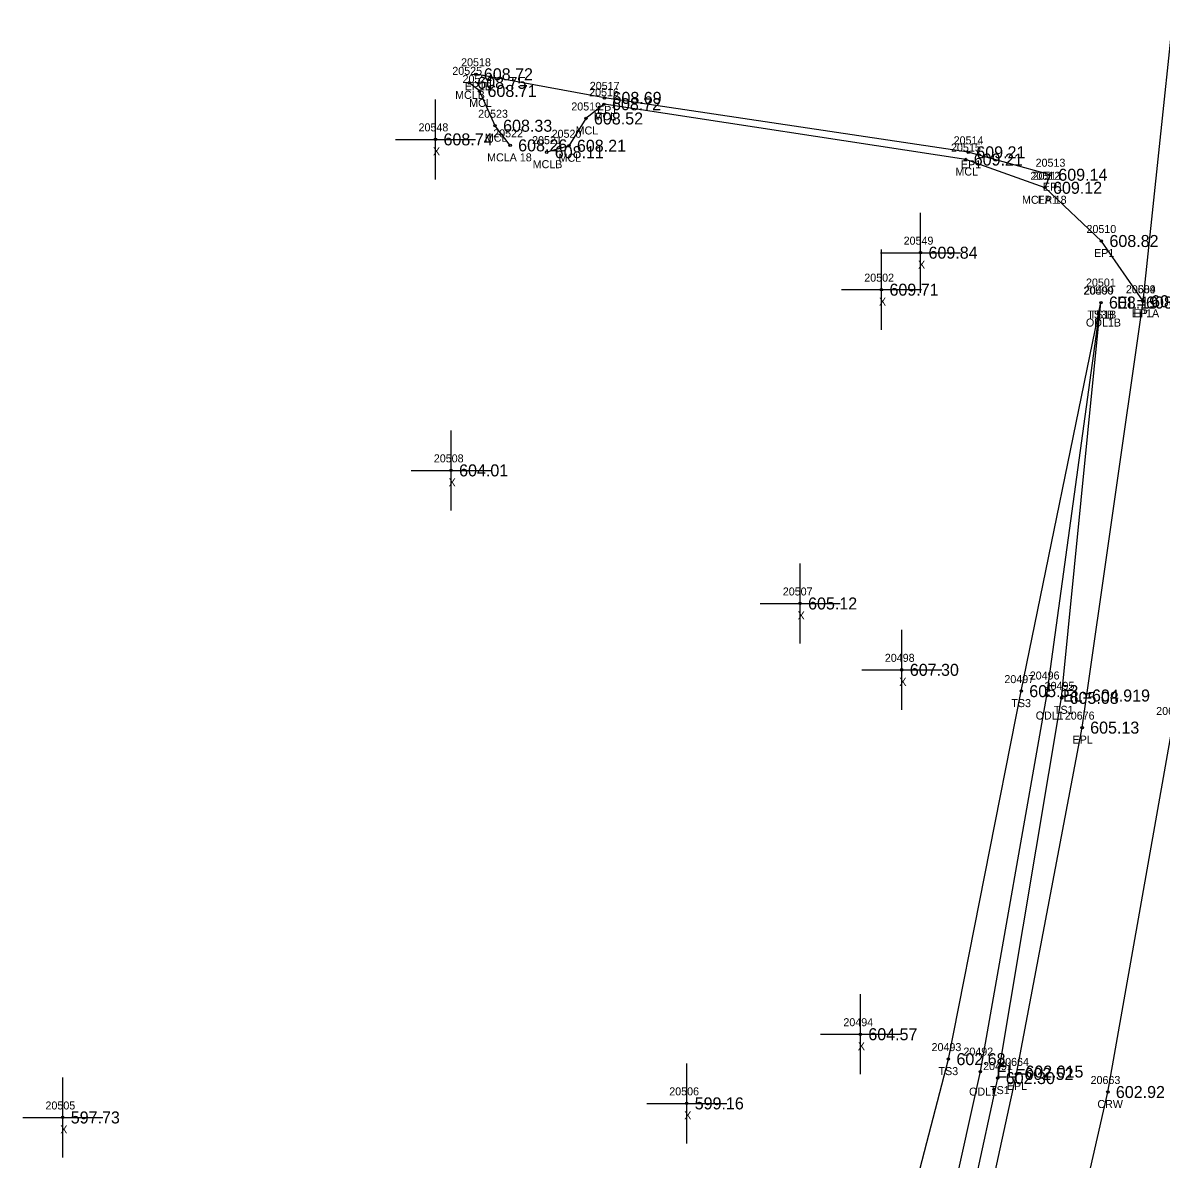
# Model space of a CAD drawing. Extents: x 1695443 to 1696344, y 1087542 to 1090645.
# Drawn here: x 1695674.7 to 1695817, y 1089816.1 to 1089958.1 of the extents above; entities that cross this region are included whole.
import ezdxf

# ---------------------------------------------------------------- set-up
doc = ezdxf.new("R2010")
doc.units = 0
for name, color, linetype in [('RD_DTM_BkLn1', 7, 'Continuous'), ('RD_DTM_BkLn2', 7, 'Continuous'), ('RD_DTM_BkLn_txCode', 7, 'Continuous'), ('RD_EX_Conc', 7, 'Continuous'), ('RD_EX_Conc_txCode', 7, 'Continuous'), ('RD_EX_H2O', 7, 'Continuous'), ('RD_EX_H2O_txCode', 7, 'Continuous'), ('RD_EX_Misc', 7, 'Continuous'), ('RD_EX_Misc_txCode', 7, 'Continuous'), ('RD_EX_Road', 7, 'Continuous'), ('RD_EX_Road_txCode', 7, 'Continuous'), ('RD_EX_TX_Conc_ELEV', 7, 'Continuous'), ('RD_EX_TX_H2O_ELEV', 7, 'Continuous'), ('RD_EX_TX_Misc_ELEV', 7, 'Continuous'), ('RD_EX_TX_Road_ELEV', 7, 'Continuous'), ('RD_HC_Survey_ELEV', 7, 'Continuous'), ('RD_HC_Survey_txCode', 7, 'Continuous'), ('RD_SMD_Locator', 7, 'Continuous')]:
    doc.layers.add(name, color=color, linetype=linetype)

msp = doc.modelspace()

# ---------------------------------------------------------------- linework, layer by layer
at = {"layer": 'RD_DTM_BkLn1'}
msp.add_lwpolyline([(1695813.78, 1089148.1), (1695785.55, 1089189.03), (1695758.89, 1089235.87), (1695740.64, 1089279.02), (1695725.17, 1089334.02), (1695718.27, 1089382.65), (1695717.41, 1089435.13), (1695722.03, 1089482.62), (1695732.64, 1089534.75), (1695759.85, 1089631.43), (1695787.11, 1089727.89), (1695798.89, 1089774.41), (1695810.31, 1089824.5), (1695818.49, 1089870.61), (1695825.85, 1089922.33), (1695831.69, 1089976.57), (1695835.49, 1090019.27), (1695844.06, 1090117.91), (1695852.56, 1090215.73), (1695861.78, 1090313.02), (1695870.8, 1090411.68), (1695879.44, 1090510.15), (1695888.04, 1090606.94)], dxfattribs=at)
at = {"layer": 'RD_DTM_BkLn2'}
for points in [[(1695696.87, 1089328.65), (1695685.13, 1089358.98), (1695692.41, 1089382.13), (1695691.76, 1089435.56), (1695699.73, 1089488.72), (1695712.17, 1089543.62), (1695742.06, 1089638.06), (1695765.36, 1089733.76), (1695777.86, 1089780.36), (1695790.39, 1089828.61), (1695799.49, 1089874.59), (1695809.45, 1089923.14)], [(1695802.49, 1089139.56), (1695797.31, 1089139.87), (1695796.55, 1089145.92), (1695767.85, 1089172.77), (1695752.08, 1089198.99), (1695743.04, 1089224.25), (1695723.93, 1089271.63), (1695706.46, 1089330), (1695701.78, 1089380.95), (1695703.12, 1089435.75), (1695708.88, 1089486.48), (1695720.72, 1089539.1), (1695747.1, 1089636.56), (1695773.41, 1089730.59), (1695786.04, 1089777.66), (1695796.55, 1089826.24), (1695804.53, 1089873.75), (1695809.45, 1089923.14)]]:
    msp.add_lwpolyline(points, dxfattribs=at)
at = {"layer": 'RD_EX_Conc'}
for points in [[(1695735.62, 1089942.78), (1695733.74, 1089945.23), (1695731.79, 1089949.58), (1695730.51, 1089950.59)], [(1695802.46, 1089937.48), (1695792.55, 1089941.01), (1695747.35, 1089947.92), (1695745.09, 1089946.14), (1695742.96, 1089942.73), (1695740.19, 1089941.93)]]:
    msp.add_lwpolyline(points, dxfattribs=at)
at = {"layer": 'RD_EX_H2O'}
msp.add_lwpolyline([(1695696.87, 1089328.65), (1695699.57, 1089380.43), (1695700.06, 1089435.96), (1695707.01, 1089487.43), (1695718.96, 1089539.87), (1695744.93, 1089637.33), (1695772.06, 1089731.31), (1695783.6, 1089778.47), (1695794.38, 1089827.05), (1695802.7, 1089874.04), (1695809.45, 1089923.14)], dxfattribs=at)
at = {"layer": 'RD_EX_Misc'}
for p, q in [((1695726.29, 1089938.53), (1695726.29, 1089948.53)), ((1695721.29, 1089943.53), (1695731.29, 1089943.53)), ((1695786.9, 1089924.37), (1695786.9, 1089934.37)), ((1695782.02, 1089919.75), (1695782.02, 1089929.75)), ((1695781.9, 1089929.37), (1695791.9, 1089929.37)), ((1695777.02, 1089924.75), (1695787.02, 1089924.75)), ((1695728.24, 1089897.17), (1695728.24, 1089907.17)), ((1695723.24, 1089902.17), (1695733.24, 1089902.17)), ((1695771.85, 1089880.54), (1695771.85, 1089890.54)), ((1695766.85, 1089885.54), (1695776.85, 1089885.54)), ((1695784.56, 1089872.25), (1695784.56, 1089882.25)), ((1695779.56, 1089877.25), (1695789.56, 1089877.25)), ((1695779.38, 1089826.72), (1695779.38, 1089836.72)), ((1695774.38, 1089831.72), (1695784.38, 1089831.72)), ((1695757.68, 1089818.08), (1695757.68, 1089828.08)), ((1695679.71, 1089816.32), (1695679.71, 1089826.32)), ((1695752.68, 1089823.08), (1695762.68, 1089823.08)), ((1695674.71, 1089821.32), (1695684.71, 1089821.32))]:
    msp.add_line(p, q, dxfattribs=at)
at = {"layer": 'RD_EX_Road'}
for points in [[(1695813.78, 1089148.1), (1695805.56, 1089142.08), (1695776.44, 1089183.94), (1695749.27, 1089231.88), (1695730.49, 1089275.72), (1695714.87, 1089332.12), (1695707.87, 1089381.72), (1695706.58, 1089435.34), (1695711.58, 1089484.26), (1695722.15, 1089537.59), (1695749.04, 1089634.88), (1695776.11, 1089730.43), (1695788.13, 1089777.42), (1695798.89, 1089826.76), (1695807.1, 1089870.03), (1695814.71, 1089923.3), (1695820.51, 1089978.16), (1695824.04, 1090019.79), (1695832.76, 1090119.06), (1695841.25, 1090216.76), (1695850.36, 1090314.41), (1695859.24, 1090411.82), (1695868.09, 1090511.63), (1695876.75, 1090608.38)], [(1695814.71, 1089923.3), (1695809.51, 1089930.83), (1695802.46, 1089937.48), (1695803.12, 1089939.11), (1695792.87, 1089941.91), (1695747.41, 1089948.71), (1695731.33, 1089951.66)]]:
    msp.add_lwpolyline(points, dxfattribs=at)
at = {"layer": 'RD_SMD_Locator'}
for centre in [(1695731.33, 1089951.66), (1695730.51, 1089950.59), (1695731.79, 1089949.58), (1695747.41, 1089948.71), (1695747.35, 1089947.92), (1695733.74, 1089945.23), (1695745.09, 1089946.14), (1695726.29, 1089943.53), (1695735.62, 1089942.78), (1695742.96, 1089942.73), (1695740.19, 1089941.93), (1695792.55, 1089941.01), (1695792.87, 1089941.91), (1695803.12, 1089939.11), (1695802.46, 1089937.48), (1695802.46, 1089937.48), (1695809.51, 1089930.83), (1695786.9, 1089929.37), (1695782.02, 1089924.75), (1695809.45, 1089923.14), (1695809.45, 1089923.14), (1695809.45, 1089923.14), (1695814.71, 1089923.3), (1695814.71, 1089923.3), (1695728.24, 1089902.17), (1695771.85, 1089885.54), (1695784.56, 1089877.25), (1695799.49, 1089874.59), (1695802.7, 1089874.04), (1695804.53, 1089873.75), (1695807.1, 1089870.03), (1695779.38, 1089831.72), (1695790.39, 1089828.61), (1695794.38, 1089827.05), (1695796.55, 1089826.24), (1695798.89, 1089826.76), (1695810.31, 1089824.5), (1695757.68, 1089823.08), (1695679.71, 1089821.32)]:
    msp.add_circle(centre, 0.15, dxfattribs=at)

# ---------------------------------------------------------------- texts
at = {"layer": 'RD_DTM_BkLn_txCode'}
for s, p in [('20500', (1695807.26, 1089924.14)), ('20499', (1695807.33, 1089924.14)), ('TS3B', (1695807.74, 1089921.14)), ('TS1B', (1695808.02, 1089921.14)), ('20497', (1695797.38, 1089875.59)), ('20495', (1695802.41, 1089874.75)), ('TS3', (1695798.25, 1089872.59)), ('TS1', (1695803.57, 1089871.75)), ('20493', (1695788.28, 1089829.61)), ('TS3', (1695789.15, 1089826.61)), ('20491', (1695794.72, 1089827.24)), ('TS1', (1695795.59, 1089824.24))]:
    msp.add_text(s, height=1, dxfattribs=at).set_placement(p)
at = {"layer": 'RD_EX_Conc_txCode'}
for s, p in [('20525', (1695728.39, 1089951.59)), ('20524', (1695729.67, 1089950.58)), ('MCLB', (1695728.74, 1089948.59)), ('20516', (1695745.49, 1089948.92)), ('MCL', (1695730.5, 1089947.58)), ('20519', (1695743.26, 1089947.14)), ('20523', (1695731.62, 1089946.23)), ('MCL', (1695746.05, 1089945.92)), ('MCL', (1695732.45, 1089943.23)), ('20522', (1695733.5, 1089943.78)), ('20521', (1695738.36, 1089942.93)), ('20520', (1695740.8, 1089943.73)), ('MCL', (1695743.8, 1089944.14)), ('20515', (1695790.71, 1089942.01)), ('MCLA 18', (1695732.74, 1089940.78)), ('MCL', (1695741.67, 1089940.73)), ('MCLB', (1695738.43, 1089939.93)), ('MCL', (1695791.26, 1089939.01)), ('20512', (1695800.63, 1089938.48)), ('MCLA 18', (1695799.58, 1089935.48))]:
    msp.add_text(s, height=1, dxfattribs=at).set_placement(p)
at = {"layer": 'RD_EX_H2O_txCode'}
for s, p in [('20501', (1695807.58, 1089925.14)), ('ODL1B', (1695807.57, 1089920.14)), ('20496', (1695800.55, 1089876.04)), ('ODL1', (1695801.29, 1089871.04)), ('20492', (1695792.26, 1089829.05)), ('ODL1', (1695792.97, 1089824.05))]:
    msp.add_text(s, height=1, dxfattribs=at).set_placement(p)
at = {"layer": 'RD_EX_Misc_txCode'}
for s, p in [('20548', (1695724.17, 1089944.53)), ('X', (1695725.97, 1089941.53)), ('20549', (1695784.79, 1089930.37)), ('X', (1695786.59, 1089927.37)), ('20502', (1695779.87, 1089925.75)), ('X', (1695781.71, 1089922.75)), ('20508', (1695726.08, 1089903.17)), ('X', (1695727.92, 1089900.17)), ('20507', (1695769.69, 1089886.54)), ('X', (1695771.54, 1089883.54)), ('20498', (1695782.44, 1089878.25)), ('X', (1695784.25, 1089875.25)), ('20494', (1695777.26, 1089832.72)), ('X', (1695779.07, 1089829.72)), ('20506', (1695755.5, 1089824.08)), ('20505', (1695677.55, 1089822.32)), ('X', (1695757.37, 1089821.08)), ('X', (1695679.4, 1089819.32))]:
    msp.add_text(s, height=1, dxfattribs=at).set_placement(p)
at = {"layer": 'RD_EX_Road_txCode'}
for s, p in [('20518', (1695729.49, 1089952.66)), ('EP1B', (1695729.94, 1089949.66)), ('20517', (1695745.57, 1089949.71)), ('EP1', (1695746.48, 1089946.71)), ('20514', (1695791.04, 1089942.91)), ('20513', (1695801.28, 1089940.11)), ('EP1', (1695791.95, 1089939.91)), ('20511', (1695800.91, 1089938.48)), ('EP1', (1695802.19, 1089937.11)), ('EP1', (1695801.54, 1089935.48)), ('20510', (1695807.64, 1089931.83)), ('EP1', (1695808.59, 1089928.83)), ('20509', (1695812.56, 1089924.3)), ('20684', (1695812.57, 1089924.3)), ('EP1A', (1695813.3, 1089921.3)), ('EPL', (1695813.51, 1089921.3)), ('20676', (1695804.93, 1089871.03)), ('EPL', (1695805.9, 1089868.03)), ('20664', (1695796.73, 1089827.76)), ('EPL', (1695797.69, 1089824.76))]:
    msp.add_text(s, height=1, dxfattribs=at).set_placement(p)
at = {"layer": 'RD_EX_TX_Conc_ELEV'}
for s, p in [('608.75', (1695731.51, 1089949.84)), ('608.71', (1695732.79, 1089948.83)), ('608.72', (1695748.35, 1089947.17)), ('608.52', (1695746.09, 1089945.39)), ('608.33', (1695734.74, 1089944.48)), ('608.26', (1695736.62, 1089942.03)), ('608.11', (1695741.19, 1089941.18)), ('608.21', (1695743.96, 1089941.98)), ('609.21', (1695793.55, 1089940.26)), ('609.12', (1695803.46, 1089936.73))]:
    msp.add_text(s, height=1.5, dxfattribs=at).set_placement(p)
at = {"layer": 'RD_EX_TX_H2O_ELEV'}
for s, p in [('EL=608.191', (1695811.45, 1089922.39)), ('EL=604.919', (1695804.7, 1089873.29)), ('EL=602.015', (1695796.38, 1089826.3))]:
    msp.add_text(s, height=1.5, dxfattribs=at).set_placement(p)
at = {"layer": 'RD_EX_TX_Misc_ELEV'}
for s, p in [('608.74', (1695727.29, 1089942.78)), ('609.84', (1695787.9, 1089928.62)), ('609.71', (1695783.02, 1089924)), ('608.19', (1695810.45, 1089922.39)), ('608.19', (1695810.45, 1089922.39)), ('604.01', (1695729.24, 1089901.42)), ('605.12', (1695772.85, 1089884.79)), ('607.30', (1695785.56, 1089876.5)), ('605.53', (1695800.49, 1089873.84)), ('605.08', (1695805.53, 1089873)), ('604.57', (1695780.38, 1089830.97)), ('602.68', (1695791.39, 1089827.86)), ('602.30', (1695797.55, 1089825.49)), ('599.16', (1695758.68, 1089822.33)), ('597.73', (1695680.71, 1089820.57))]:
    msp.add_text(s, height=1.5, dxfattribs=at).set_placement(p)
at = {"layer": 'RD_EX_TX_Road_ELEV'}
for s, p in [('608.72', (1695732.33, 1089950.91)), ('608.69', (1695748.41, 1089947.96)), ('609.21', (1695793.87, 1089941.16)), ('609.14', (1695804.12, 1089938.36)), ('609.12', (1695803.46, 1089936.73)), ('608.82', (1695810.51, 1089930.08)), ('608.53', (1695815.71, 1089922.55)), ('608.53', (1695815.71, 1089922.55)), ('605.13', (1695808.1, 1089869.28)), ('602.52', (1695799.89, 1089826.01))]:
    msp.add_text(s, height=1.5, dxfattribs=at).set_placement(p)
at = {"layer": 'RD_HC_Survey_ELEV'}
msp.add_text('602.92', height=1.5, dxfattribs=at).set_placement((1695811.31, 1089823.75))
at = {"layer": 'RD_HC_Survey_txCode'}
for s, p in [('20677', (1695816.35, 1089871.61)), ('20663', (1695808.15, 1089825.5)), ('CRW', (1695809, 1089822.5))]:
    msp.add_text(s, height=1, dxfattribs=at).set_placement(p)

doc.saveas('drawing.dxf')
